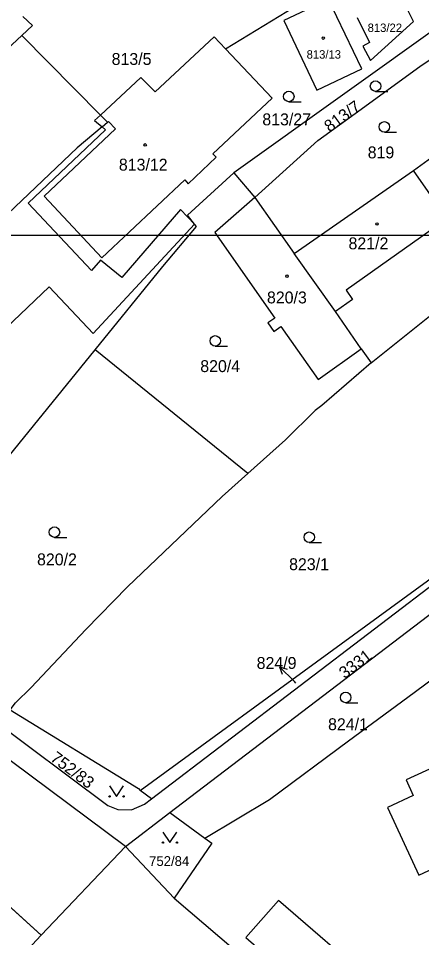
# Model space of a CAD drawing. Extents: x -496682 to -495907, y -1088575 to -1088018.
# Drawn here: x -496329.2 to -496271.6, y -1088264.6 to -1088133.3 of the extents above; entities that cross this region are included whole.
import ezdxf

# ---------------------------------------------------------------- set-up
doc = ezdxf.new("R2010")
doc.units = 0
for name, color, linetype in [('Hranice parcel', 7, 'Continuous'), ('Parcelní čísla', 7, 'Continuous'), ('Pop  PČ popisy', 7, 'Continuous'), ('Vnitřní kresba', 7, 'Continuous'), ('Vrstva 54', 7, 'Continuous'), ('Vrstva 63', 7, 'Continuous'), ('Značky budov', 7, 'Continuous'), ('Značky kultur', 7, 'Continuous')]:
    doc.layers.add(name, color=color, linetype=linetype)

msp = doc.modelspace()

# ---------------------------------------------------------------- linework, layer by layer
at = {"layer": 'Hranice parcel'}
for p, q in [((-496299.6, -1088137.62), (-496287.5, -1088130.23)), ((-496350.76, -1088156.43), (-496328.71, -1088135.71)), ((-496328.71, -1088135.71), (-496317.45, -1088147.13)), ((-496317.45, -1088147.13), (-496316.44, -1088148.1)), ((-496317.24, -1088148.77), (-496316.44, -1088148.1)), ((-496272.8, -1088155.01), (-496263.79, -1088148.47)), ((-496298.45, -1088155.33), (-496295.42, -1088158.88)), ((-496289.8, -1088166.88), (-496272.8, -1088155.01)), ((-496268.02, -1088161.9), (-496272.8, -1088155.01)), ((-496295.42, -1088158.88), (-496289.8, -1088166.88)), ((-496283.92, -1088175.15), (-496289.8, -1088166.88)), ((-496278.83, -1088182.48), (-496265.29, -1088171.61)), ((-496280.24, -1088180.51), (-496283.92, -1088175.15)), ((-496296.45, -1088198.31), (-496318.2, -1088180.61)), ((-496280.24, -1088180.51), (-496278.83, -1088182.48)), ((-496310.18, -1088244.79), (-496311.81, -1088243.59)), ((-496302.57, -1088250.38), (-496293.33, -1088244.86)), ((-496313.9, -1088251.57), (-496307.55, -1088246.72)), ((-496307.55, -1088246.72), (-496302.57, -1088250.38)), ((-496325.94, -1088264.24), (-496313.9, -1088251.57)), ((-496313.9, -1088251.57), (-496306.94, -1088258.98)), ((-496325.94, -1088264.24), (-496332.38, -1088258.39))]:
    msp.add_line(p, q, dxfattribs=at)
for points in [[(-496284.92, -1088130.53), (-496291.31, -1088133.56), (-496286.59, -1088143.52), (-496280.17, -1088140.48), (-496284.92, -1088130.53)], [(-496280.81, -1088133.14), (-496279.08, -1088136.73), (-496280.02, -1088137.23), (-496278.91, -1088139.32), (-496272.78, -1088133.72), (-496273.98, -1088131.36)], [(-496328.55, -1088133.03), (-496327.18, -1088134.28), (-496328.71, -1088135.71)], [(-496265.89, -1088136.18), (-496267.72, -1088133.38), (-496298.45, -1088155.33)], [(-496317.45, -1088147.13), (-496311.72, -1088141.73), (-496309.67, -1088143.77), (-496301.22, -1088135.9), (-496299.6, -1088137.62)], [(-496295.42, -1088158.88), (-496286.46, -1088150.74), (-496280.26, -1088146.23), (-496271.7, -1088140.01), (-496265.89, -1088136.18)], [(-496316.44, -1088148.1), (-496316.33, -1088148), (-496315.31, -1088149.08), (-496325.51, -1088158.67), (-496317.28, -1088167.48), (-496305.43, -1088156.36), (-496304.95, -1088156.9), (-496300.93, -1088153.13), (-496301.44, -1088152.61), (-496292.98, -1088144.67), (-496299.6, -1088137.62)], [(-496317.24, -1088148.77), (-496320.78, -1088151.75), (-496343.54, -1088173.37)], [(-496304.04, -1088162.67), (-496306.05, -1088160.58), (-496314.41, -1088170.29), (-496317.47, -1088167.8), (-496318.76, -1088169.3), (-496327.78, -1088159.67), (-496316.73, -1088149.19), (-496317.24, -1088148.77)], [(-496304.04, -1088162.67), (-496305.02, -1088161.37), (-496298.45, -1088155.33)], [(-496295.42, -1088158.88), (-496301.16, -1088163.87), (-496292.58, -1088176.09), (-496293.56, -1088176.78), (-496292.71, -1088177.99), (-496291.73, -1088177.3), (-496286.4, -1088184.88), (-496280.24, -1088180.51)], [(-496268.02, -1088161.9), (-496282.4, -1088172.11), (-496281.47, -1088173.42), (-496283.92, -1088175.15)], [(-496304.04, -1088162.67), (-496318.49, -1088178.29), (-496324.77, -1088171.65), (-496342.29, -1088188.3), (-496343.55, -1088187.04), (-496349.76, -1088195.32)], [(-496318.2, -1088180.61), (-496308.55, -1088168.74), (-496303.76, -1088163.03), (-496304.04, -1088162.67)], [(-496346.16, -1088215.94), (-496333.82, -1088199.82), (-496318.2, -1088180.61)], [(-496278.83, -1088182.48), (-496285.87, -1088188.57), (-496286.81, -1088189.29), (-496291.03, -1088193.47), (-496296.45, -1088198.31)], [(-496311.81, -1088243.59), (-496254.42, -1088201.7), (-496253.97, -1088194.3)], [(-496330.37, -1088232.05), (-496329.58, -1088231.08), (-496327.35, -1088228.88), (-496319.53, -1088220.58), (-496313.61, -1088214.48), (-496300.1, -1088201.57), (-496296.45, -1088198.31)], [(-496310.18, -1088244.79), (-496257.12, -1088204.31), (-496254.49, -1088202.87), (-496251.61, -1088202), (-496250.98, -1088201.92)], [(-496307.55, -1088246.72), (-496254.8, -1088206.49), (-496251.12, -1088205.07), (-496249.48, -1088204.87)], [(-496293.33, -1088244.86), (-496282.06, -1088236.51), (-496272.7, -1088229.58), (-496261.37, -1088221.14)], [(-496313.9, -1088251.57), (-496335.64, -1088235.39), (-496340.47, -1088231.82), (-496349.2, -1088225.23), (-496347.19, -1088222.58)], [(-496347.19, -1088222.58), (-496338.46, -1088229.24), (-496333.64, -1088232.87), (-496316.4, -1088245.74), (-496315, -1088246.3), (-496313.02, -1088246.35), (-496311.19, -1088245.56), (-496310.18, -1088244.79)], [(-496330.37, -1088232.05), (-496312.02, -1088243.31), (-496311.81, -1088243.59)], [(-496266.56, -1088238.74), (-496273.85, -1088242.06), (-496272.81, -1088244.31), (-496276.5, -1088246.03), (-496272.01, -1088255.68), (-496261.03, -1088250.54)], [(-496302.57, -1088250.38), (-496301.59, -1088251.1), (-496306.94, -1088258.98)], [(-496306.94, -1088258.98), (-496285.12, -1088277.63), (-496271.2, -1088289.24), (-496248.36, -1088307.94), (-496243.5, -1088305.4)], [(-496292.05, -1088259.28), (-496296.7, -1088264.61), (-496269.47, -1088288.37), (-496264.72, -1088282.93), (-496292.05, -1088259.28)], [(-496295.37, -1088310.06), (-496327.63, -1088281.05), (-496324.32, -1088278.18), (-496332.44, -1088271.21), (-496325.94, -1088264.24)]]:
    msp.add_lwpolyline(points, dxfattribs=at)
at = {"layer": 'Pop  PČ popisy'}
for p, q in [((-496289.77, -1088228.03), (-496291.89, -1088225.91)), ((-496291.89, -1088225.91), (-496290.83, -1088226.26)), ((-496291.89, -1088225.91), (-496291.54, -1088226.97)), ((-496289.57, -1088228.24), (-496289.77, -1088228.03))]:
    msp.add_line(p, q, dxfattribs=at)
at = {"layer": 'Vnitřní kresba'}
for p, q in [((-496317.45, -1088147.13), (-496318.3, -1088147.89)), ((-496318.3, -1088147.89), (-496317.24, -1088148.77))]:
    msp.add_line(p, q, dxfattribs=at)
at = {"layer": 'Vrstva 54'}
msp.add_lwpolyline([(-496428.63, -1088193.79), (-496375.97, -1088240.32), (-496368.91, -1088246.59), (-496342.71, -1088269.83), (-496341.4, -1088268.22), (-496333.89, -1088259.9), (-496332.38, -1088258.39), (-496325.94, -1088264.24), (-496332.44, -1088271.21), (-496324.32, -1088278.18), (-496327.63, -1088281.05), (-496295.37, -1088310.06), (-496296.07, -1088310.84), (-496290.49, -1088315.87), (-496286.66, -1088311.63), (-496280.68, -1088316.78), (-496283.68, -1088320.49), (-496250.52, -1088349.65), (-496235.04, -1088333.66)], dxfattribs=at)
at = {"layer": 'Vrstva 63'}
msp.add_lwpolyline([(-496137.35, -1088164.24), (-496137.35, -1088461.24), (-496557.35, -1088461.24), (-496557.35, -1088164.24)], close=True, dxfattribs=at)
at = {"layer": 'Značky budov'}
for centre in [(-496285.66, -1088136.1), (-496311.09, -1088151.35), (-496278, -1088162.65), (-496290.84, -1088170.11)]:
    msp.add_circle(centre, 0.175, dxfattribs=at)
at = {"layer": 'Značky kultur'}
for p, q in [((-496278.2, -1088143.71), (-496276.45, -1088143.71)), ((-496290.59, -1088145.18), (-496288.84, -1088145.18)), ((-496276.94, -1088149.53), (-496275.19, -1088149.53)), ((-496301.08, -1088180.1), (-496299.33, -1088180.1)), ((-496324.03, -1088207.42), (-496322.28, -1088207.42)), ((-496287.66, -1088208.15), (-496285.91, -1088208.15)), ((-496282.46, -1088231.05), (-496280.71, -1088231.05))]:
    msp.add_line(p, q, dxfattribs=at)
for points in [[(-496316.17, -1088242.93), (-496315.17, -1088244.43), (-496314.17, -1088242.93)], [(-496308.56, -1088249.53), (-496307.56, -1088251.03), (-496306.56, -1088249.53)]]:
    msp.add_lwpolyline(points, dxfattribs=at)
for centre, radius in [((-496278.2, -1088142.96), 0.75), ((-496290.59, -1088144.43), 0.75), ((-496276.94, -1088148.78), 0.75), ((-496301.08, -1088179.35), 0.75), ((-496324.03, -1088206.67), 0.75), ((-496287.66, -1088207.4), 0.75), ((-496282.46, -1088230.3), 0.75), ((-496316.17, -1088244.43), 0.1), ((-496314.17, -1088244.43), 0.1), ((-496308.56, -1088251.03), 0.1), ((-496306.56, -1088251.03), 0.1)]:
    msp.add_circle(centre, radius, dxfattribs=at)

# ---------------------------------------------------------------- texts
at = {"layer": 'Parcelní čísla'}
for s, height, p in [('813/22', 1.2, (-496279.33, -1088135.22)), ('813/5', 1.7, (-496315.87, -1088139.93)), ('813/13', 1.2, (-496288.04, -1088139.03)), ('813/27', 1.7, (-496294.36, -1088148.56)), ('819', 1.7, (-496279.32, -1088153.28)), ('813/12', 1.7, (-496314.84, -1088155.03)), ('821/2', 1.7, (-496282.06, -1088166.27)), ('820/3', 1.7, (-496293.7, -1088174)), ('820/4', 1.7, (-496303.22, -1088183.81)), ('820/2', 1.7, (-496326.52, -1088211.42)), ('823/1', 1.7, (-496290.54, -1088212.11)), ('824/9', 1.7, (-496295.17, -1088226.22)), ('824/1', 1.7, (-496284.98, -1088234.97)), ('752/84', 1.4, (-496310.52, -1088254.37))]:
    msp.add_text(s, height=height, dxfattribs=at).set_placement(p)
for s, rotation, p in [('813/7', 36, (-496284.76, -1088149.61)), ('3331', 37, (-496282.61, -1088227.7)), ('752/83', 323, (-496324.74, -1088239.23))]:
    msp.add_text(s, height=1.7, rotation=rotation, dxfattribs=at).set_placement(p)

doc.saveas('drawing.dxf')
